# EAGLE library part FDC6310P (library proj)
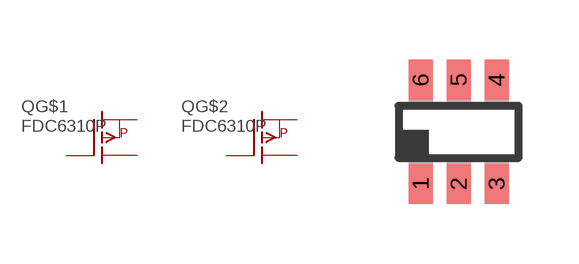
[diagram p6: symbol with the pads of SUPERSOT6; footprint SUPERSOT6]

Designator prefix Q; gates G$1=FET-DUAL-P G$2=FET-DUAL-P

## FDC6310P  [SUPERSOT6]
1  G$1:GP  pas
2  G$2:SP  pas
3  G$2:GP  pas
4  G$2:DP  pas
5  G$1:SP  pas
6  G$1:DP  pas

## Footprint SUPERSOT6 (pad centres in mm)
Fairchild SuperSOT6
smd 0.6 x 1: 1 -0.95,-1.3; 2 0,-1.3; 3 0.95,-1.3; 4 0.95,1.3; 5 0,1.3; 6 -0.95,1.3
